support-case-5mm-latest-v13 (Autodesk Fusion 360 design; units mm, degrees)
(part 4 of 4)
sketch "Sketch74" plane through (90.7, 0, 0) normal (1, 0, 0) x axis (0, 1, 0)
  line L1 (53.302, -2.019) -> (35.6, -2.019)
  line L2 (53.302, 26.6) -> (53.302, -2.019)
  line L3 (2.6862, 26.6) -> (53.302, 26.6)
  line L4 (2.6862, -2.019) -> (2.6862, 26.6)
  line L5 (18.9875, -2.019) -> (2.6862, -2.019)
  line L6 (18.9875, 0.4) -> (18.9875, -2.019)
  line L7 (33.6, 2.4) -> (20.9875, 2.4)
  line L8 (35.6, -2.019) -> (35.6, 0.4)
  line L9 (41.9463, 5.5134) -> (37.5941, 5.5134)
  line L10 (41.7017, 1.4134) -> (41.9463, 1.4134)
  line L11 (40.5558, 1.4134) -> (41.7017, 1.4134)
  line L12 (39.1616, 1.4134) -> (40.5558, 1.4134)
  line L13 (37.8441, 1.4134) -> (39.1616, 1.4134)
  line L14 (37.5941, 1.4134) -> (37.8441, 1.4134)
  line L15 (23.4568, 21.6159) -> (25.2548, 23.2889)
  line L16 (5.2077, 18.9187) -> (4.2077, 20.7353)
  line L17 (40.1676, 9.6517) -> (39.2193, 8.064)
  line L18 (6.4, 23.1109) -> (7.4, 24.3219)
  line L19 (42.5596, 22.7691) -> (43.0662, 24.2031)
  line L20 (41.7469, 24.8866) -> (41.2404, 23.4527)
  line L21 (32.0437, 22.2712) -> (33.4647, 19.745)
  line L22 (35.4902, 15.0887) -> (34.5243, 17.4666)
  line L23 (39.4648, 19.4776) -> (39.4648, 23.3591)
  line L24 (25.9773, 6.721) -> (26.4364, 4.7387)
  line L25 (35.5538, 21.4686) -> (34.1329, 23.9948)
  line L26 (31.0052, 11.1037) -> (31.7185, 10.588)
  line L27 (1.4083, 12.8829) -> (2.8013, 15.1808)
  line L28 (32.9788, 16.2652) -> (33.9447, 13.8873)
  line L29 (18.8086, 7.587) -> (17.9793, 9.8452)
  line L30 (50.6417, 0.8202) -> (50.2324, 0.2055)
  line L31 (36.9, 23.3591) -> (36.9, 19.4776)
  line L32 (3.3483, 7.513) -> (4.3483, 10.5407)
  line L33 (2.4517, 11.4595) -> (1.4517, 8.4318)
  line L34 (17.1621, 9.4051) -> (17.9914, 7.1468)
  line L35 (33.0246, 12.4489) -> (32.3113, 12.9647)
  line L36 (18.5778, 15.5074) -> (19.089, 10.0002)
  line L37 (20.7281, 10.2234) -> (20.2169, 15.7306)
  line L38 (27.6816, 5.1617) -> (27.2225, 7.144)
  line L39 (19.5307, 19.8249) -> (22.16, 15.944)
  line L40 (3.4024, 25.3699) -> (2.7109, 24.2292)
  line L41 (10.158, 8.4337) -> (10.6467, 10.7711)
  line L42 (3.3478, 1.0989) -> (4.3745, -0.8093)
  line L43 (45.475, 24.0646) -> (46.475, 21.6425)
  line L44 (17.8581, 22.3319) -> (16.0794, 25.106)
  line L45 (1.7816, 16.0876) -> (0.3885, 13.7896)
  line L46 (23.8986, 17.6716) -> (21.2693, 21.5525)
  line L47 (3.7061, 23.3443) -> (4.3976, 24.485)
  line L48 (1.8109, 22.8539) -> (0.9351, 25.0418)
  line L49 (9.7695, 4.8354) -> (8.2332, 1.8078)
  line L50 (-0.5165, 24.1896) -> (0.3592, 22.0017)
  line L51 (6.141, 0.5848) -> (5.1143, 2.493)
  line L52 (51.59, -1.1201) -> (51.9992, -0.5054)
  line L53 (49.2483, 16.4768) -> (49.6841, 17.9192)
  line L54 (7.1055, 12.435) -> (11.5308, 19.7348)
  line L55 (55.5632, 8.2533) -> (54.5035, 10.9558)
  line L56 (53.6718, 2.0633) -> (54.6124, 4.3817)
  line L57 (8.4571, 20.1523) -> (9.15, 20.9915)
  line L58 (53.7, 23.8375) -> (50.7, 16.5711)
  line L59 (4.9, 7.3669) -> (5.9, 4.9447)
  line L60 (24.8728, 5.5249) -> (24.3728, 6.0249)
  line L61 (11.1272, 16.5692) -> (11.4959, 14.939)
  line L62 (6.4, 25.533) -> (5.4, 24.3219)
  line L63 (14.653, 23.7646) -> (16.4317, 20.9905)
  line L64 (47.325, 22.1571) -> (46.325, 24.5793)
  line L65 (9.1533, 11.2291) -> (8.6646, 8.8917)
  line L66 (48.1159, 18.614) -> (47.6802, 17.1716)
  line L67 (27.9313, 20.6361) -> (22.1786, 11.5219)
  line L68 (53.0687, 5.3003) -> (52.1282, 2.9819)
  line L69 (10.1405, 20.971) -> (5.7152, 13.6711)
  line L70 (13.1748, 24.5947) -> (12.4, 25.533)
  line L71 (40.7726, 6.7035) -> (41.7208, 8.2912)
  line L72 (2.5923, 19.4311) -> (3.5923, 17.6144)
  line L73 (51.7635, 9.5602) -> (52.6564, 11.7611)
  line L74 (53.1, 15.1178) -> (56.1, 22.3842)
  line L75 (49.0733, 22.7972) -> (49.8997, 20.6896)
  line L76 (24.2394, 24.8894) -> (22.4414, 23.2165)
  line L77 (13.3041, 15.5388) -> (12.9354, 17.169)
  line L78 (22.6272, 3.9751) -> (23.1272, 3.4751)
  line L79 (7.9, 6.1558) -> (6.9, 8.578)
  line L80 (11.4, 24.3219) -> (12.1748, 23.3836)
  line L81 (17.1803, 17.3595) -> (15.9685, 19.506)
  line L82 (51.1436, 12.6613) -> (50.2507, 10.4604)
  line L83 (54.8808, 17.4204) -> (54.1112, 15.5233)
  line L84 (50.4738, 21.0198) -> (49.6474, 23.1274)
  line L85 (25.1005, 8.8169) -> (30.8532, 17.9311)
  line L86 (40.8805, 17.1052) -> (46.2802, 3.3342)
  line L87 (14.2377, 18.0729) -> (15.4494, 15.9264)
  line L88 (55.6943, 14.5812) -> (56.464, 16.4784)
  line L89 (13.7708, 12.9212) -> (11.9937, 2.022)
  line L90 (7.65, 22.8081) -> (6.9571, 21.969)
  line L91 (9.5668, 0.8153) -> (11.1031, 3.8429)
  line L92 (38.2565, 14.808) -> (31.122, 6.5197)
  line L93 (14.9409, 1.3172) -> (16.718, 12.2164)
  line L94 (-1.1, -2.7783) -> (57.9, -2.7783)
  line L95 (32.609, 4.9036) -> (39.7435, 13.192)
  line L96 (50.3191, 5.657) -> (44.9195, 19.428)
  line L97 (53.7651, 10.5312) -> (54.8248, 7.8286)
  line L98 (15.9449, -0.1083) -> (17.5336, 3.5298)
  line L99 (19.1191, 2.8374) -> (17.5303, -0.8007)
  line L100 (16.3914, -1.2472) -> (18.6725, 3.9763)
  arc A1 centre (20.9875, 0.4) radius 2 clockwise from (18.9875, 0.4) to (20.9875, 2.4)
  arc A2 centre (33.6, 0.4) radius 2 clockwise from (33.6, 2.4) to (35.6, 0.4)
  arc A3 centre (41.9463, 3.4634) radius 2.05 clockwise from (41.9463, 5.5134) to (41.9463, 1.4134)
  arc A4 centre (37.5941, 3.4634) radius 2.05 clockwise from (37.5941, 1.4134) to (37.5941, 5.5134)
  closed curve K1 centre (18.4, 7.3669)
  closed curve K2 centre (15.2444, 12.5688)
  closed curve K3 centre (17.5707, 9.6252)
  closed curve K4 centre (32.3715, 11.5184)
  closed curve K5 centre (27.059, 4.9502)
  closed curve K6 centre (26.5999, 6.9325)
  closed curve K7 centre (31.8655, 5.7116)
  closed curve K8 centre (28.6606, 10.4917)
  closed curve K9 centre (12.2635, 11.7963)
  closed curve K10 centre (11.4, 7.3669)
  closed curve K11 centre (33.0883, 23.133)
  closed curve K12 centre (34.7175, 14.488)
  closed curve K13 centre (33.7515, 16.8659)
  closed curve K14 centre (23.6396, 10.1694)
  closed curve K15 centre (19.9085, 10.1118)
  closed curve K16 centre (31.6583, 12.0342)
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  parallel L98 L99
extrude "Extrude130" cut sketch "Sketch74" against normal blind 2.8
sketch "Sketch75" plane through (0, -3.8138, 0) normal (0, -1, 0) x axis (1, 0, 0)
  line L1 (84.2, -2.019) -> (4.6, -2.019)
  line L2 (84.2, 26.6) -> (84.2, -2.019)
  line L3 (4.6, 26.6) -> (84.2, 26.6)
  line L4 (4.6, -2.019) -> (4.6, 26.6)
  line L5 (66.3275, 20.204) -> (66.0531, 18.5962)
  line L6 (69.7087, 11.8334) -> (68.659, 10.8525)
  line L7 (2.4342, 20.7551) -> (2.0341, 19.9667)
  line L8 (5.4007, 18.5733) -> (5.8284, 20.8018)
  line L9 (11.6138, 3.0954) -> (10.1269, -0.4431)
  line L10 (4.5238, 21.1728) -> (4.096, 18.9443)
  line L11 (34.4236, 19.1639) -> (35.6936, 21.1559)
  line L12 (50.9876, 18.9404) -> (51.6298, 16.6544)
  line L13 (53.2648, 6.7818) -> (50.5709, 3.7552)
  line L14 (79.758, 14.4068) -> (79.758, 16.0903)
  line L15 (19.6345, 14.8068) -> (18.5631, 13.1676)
  line L16 (6.9567, 6.8721) -> (7.4152, 5.5068)
  line L17 (83.0491, 24.9408) -> (79.3759, 21.2565)
  line L18 (16.2289, 4.1768) -> (16.646, 2.1224)
  line L19 (20.6992, 16.5069) -> (21.1163, 17.7434)
  line L20 (42.7214, 18.2226) -> (42.3133, 16.7012)
  line L21 (11.5299, 9.2998) -> (13.972, 5.9586)
  line L22 (65.9781, 21.6037) -> (66.2842, 25.0005)
  line L23 (13.9875, 3.919) -> (13.9875, 1.4847)
  line L24 (6.0799, -0.1352) -> (4.5263, 2.913)
  line L25 (2.0102, 24.654) -> (3.1364, 23.1121)
  line L26 (15.1271, 1.4847) -> (15.1271, 3.919)
  line L27 (13.7792, 19.2179) -> (13.0569, 17.6499)
  line L28 (75.9777, -0.1832) -> (74.4989, 4.9715)
  line L29 (73.1205, 4.3857) -> (74.5993, -0.769)
  line L30 (69.4007, 9.6766) -> (70.4504, 10.6576)
  line L31 (4.3013, 24.3726) -> (3.1751, 25.9145)
  line L32 (2.5694, 5.4655) -> (2.2146, 6.8495)
  line L33 (14.1406, 16.9105) -> (14.8629, 18.4784)
  line L34 (3.4887, 2.1296) -> (5.0423, -0.9186)
  line L35 (67.1262, 9.8051) -> (71.3437, 18.4719)
  line L36 (80.797, 25.5031) -> (80.2529, 24.6752)
  line L37 (34.1619, 24.4947) -> (34.1619, 25.3852)
  line L38 (13.1032, 20.7969) -> (14.0249, 22.2071)
  line L39 (44.6849, 23.5682) -> (45.7626, 24.8067)
  line L40 (49.2171, 24.5535) -> (48.5518, 25.3633)
  line L41 (15.8325, 19.9508) -> (15.9956, 18.1421)
  line L42 (51.601, 11.8389) -> (52.7234, 8.9826)
  line L43 (63.6859, 22.3177) -> (63.3844, 24.7189)
  line L44 (48.8498, 9.8224) -> (47.3533, 5.0004)
  line L45 (46.4024, 1.7746) -> (46.3972, 3.9211)
  line L46 (20.5985, 7.418) -> (12.0847, 16.5734)
  line L47 (89, -3.6) -> (89, 28.4)
  line L48 (68.7251, 20.3596) -> (64.5076, 11.6928)
  line L49 (-2, 27.4) -> (89, 27.4)
  line L50 (-2, 28.4) -> (-2, -3.6)
  line L51 (89, 27.4) -> (89, -2.6)
  line L52 (59.5941, 8.6469) -> (56.329, 16.4708)
  line L53 (6.2954, 17.01) -> (4.0568, 5.3475)
  line L54 (-2, -2.6) -> (-2, 27.4)
  line L55 (89, 28.4) -> (-2, 28.4)
  line L56 (53.4013, 14.6609) -> (56.6664, 6.8369)
  line L57 (10.0993, 13.8384) -> (18.6132, 4.683)
  line L58 (5.5432, 4.9248) -> (7.7819, 16.5873)
  line L59 (-2, -3.6) -> (89, -3.6)
  line L60 (28.0063, 15.7339) -> (25.5219, 8.0645)
  line L61 (89, -2.6) -> (-2, -2.6)
  line L62 (29.1093, 6.343) -> (31.5937, 14.0124)
  line L63 (36.5702, 20.2977) -> (37.4886, 10.1141)
  line L64 (74.4711, 20.8505) -> (73.3253, 22.6668)
  line L65 (86.3856, 13.2262) -> (86.8678, 13.7098)
  line L66 (10.489, 3.689) -> (10.8556, 5.5991)
  line L67 (14.6001, 6.6387) -> (12.158, 9.9799)
  line L68 (74.623, 12.7502) -> (75.8256, 11.4188)
  line L69 (17.4293, 13.9143) -> (17.4293, 15.3703)
  line L70 (46.9137, -1.2094) -> (47.4316, -0.2849)
  line L71 (61.5172, 10.3053) -> (62.5376, 12.5614)
  line L72 (37.2516, 24.4317) -> (38.2032, 23.5104)
  line L73 (23.166, 22.9824) -> (21.9756, 24.5127)
  line L74 (41.0189, 10.5857) -> (40.1006, 20.7693)
  line L75 (56.533, 18.3376) -> (57.0216, 17.1668)
  line L76 (60.8879, 0.7104) -> (60.3215, -0.6556)
  line L77 (60.4977, 24.1194) -> (60.7358, 21.6443)
  line L78 (52.4803, 1.2376) -> (55.1741, 4.2642)
  line L79 (51.0499, 25.4275) -> (50.1905, 23.9384)
  line L80 (20.9378, 23.3167) -> (22.1282, 21.7864)
  line L81 (38.9926, 24.7181) -> (38.041, 25.6394)
  line L82 (58.7171, 18.1125) -> (61.268, 15.4631)
  line L83 (2.3456, 16.9649) -> (3.2227, 15.2408)
  line L84 (71.4399, 7.5697) -> (71.4045, 7.1597)
  line L85 (67.5485, 2.3996) -> (67.5515, 1.1452)
  line L86 (1.6404, 11.0419) -> (2.3688, 8.2011)
  line L87 (1.5468, 2.5042) -> (1.8665, 1.2572)
  line L88 (72.5955, 7.0073) -> (72.6309, 7.4173)
  line L89 (47.3983, 17.822) -> (44.3032, 14.3447)
  line L90 (57.199, 24.8521) -> (55.6063, 22.6977)
  line L91 (18.406, 18.4641) -> (18.2429, 20.2728)
  line L92 (45.2028, 3.9169) -> (45.208, 1.7703)
  line L93 (58.2087, 14.6147) -> (59.7175, 13.6039)
  line L94 (47.8665, 24.5292) -> (48.5318, 23.7194)
  line L95 (44.8249, 20.7679) -> (41.1449, 25.6203)
  line L96 (62.2156, 24.5015) -> (62.5172, 22.1003)
  line L97 (45.9043, 12.2335) -> (48.9994, 15.7108)
  line L98 (63.8886, 2.6664) -> (62.188, 6.2679)
  line L99 (48.9639, -0.1553) -> (49.938, -1.4397)
  line L100 (47.0075, 11.5857) -> (46.2252, 10.2303)
  line L101 (64.7983, 4.9894) -> (65.169, 6.1836)
  line L102 (54.1499, 9.813) -> (53.0275, 12.6693)
  line L103 (60.2408, 14.7611) -> (58.7321, 15.7719)
  line L104 (45.1765, 25.5622) -> (44.0988, 24.3237)
  line L105 (57.5931, 20.5219) -> (59.1858, 22.6762)
  line L106 (48.8403, 4.3168) -> (50.3368, 9.1388)
  line L107 (64.8657, 25.1898) -> (64.5596, 21.793)
  line L108 (22.5432, 19.7116) -> (17.065, 25.0157)
  line L109 (64.431, 6.5229) -> (64.0604, 5.3287)
  line L110 (55.2717, 2.9988) -> (54.2717, 1.7817)
  line L111 (50.4953, -0.8135) -> (49.5212, 0.4709)
  line L112 (34.609, 22.1803) -> (33.339, 20.1883)
  line L113 (60.6028, 5.159) -> (62.3034, 1.5575)
  line L114 (49.7536, 20.7586) -> (47.8509, 23.0339)
  line L115 (47.1794, 9.4145) -> (47.9617, 10.7699)
  line L116 (50.4509, 15.2812) -> (48.9722, 13.4074)
  line L117 (43.4727, 16.2405) -> (43.8808, 17.7618)
  line L118 (11.3914, -1.2301) -> (12.8782, 2.3083)
  line L119 (71.8969, 9.7055) -> (74.2041, 7.2494)
  line L120 (20.1914, 18.2056) -> (19.7743, 16.9691)
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  horizontal L59
  vertical L50
  horizontal L55
  vertical L47
extrude "Extrude131" cut sketch "Sketch75" against normal blind 2.8
delete_face "DeleteFace141"
delete_face "DeleteFace142"
delete_face "DeleteFace143"
extrude "Extrude132" cut sketch "Sketch75" against normal blind 2.8
extrude "Extrude133" cut of existing geometry blind -0.377
delete_face "DeleteFace144"
sketch "Sketch76" plane through (-1.8892, 0, 0) normal (-1, 0, 0) x axis (0, -1, 0)
  line L1 (-3.0601, 20.4699) -> (-15.7431, 20.4699)
  line L2 (-3.0601, 26.6) -> (-3.0601, 20.4699)
  line L3 (-52.9282, 26.6) -> (-3.0601, 26.6)
  line L4 (-52.9282, 18.2699) -> (-52.9282, 26.6)
  line L5 (-38.2931, 18.2699) -> (-52.9282, 18.2699)
  line L6 (-36.2931, 3.4699) -> (-36.2931, 16.2699)
  line L7 (-52.9282, 1.4699) -> (-38.2931, 1.4699)
  line L8 (-52.9282, -2.019) -> (-52.9282, 1.4699)
  line L9 (-3.0601, -2.019) -> (-52.9282, -2.019)
  line L10 (-3.0601, 1.4699) -> (-3.0601, -2.019)
  line L11 (-15.7431, 1.4699) -> (-3.0601, 1.4699)
  line L12 (-17.7431, 18.4699) -> (-17.7431, 3.4699)
  line L13 (-18.1431, 3.4699) -> (-18.1431, 18.4699)
  line L14 (-33.6431, 1.4699) -> (-20.1431, 1.4699)
  line L15 (-35.6431, 18.4699) -> (-35.6431, 3.4699)
  line L16 (-20.1431, 20.4699) -> (-33.6431, 20.4699)
  line L17 (-41, 22) -> (-38, 25)
  line L18 (-36, 23) -> (-39, 20)
  line L19 (-41, 20) -> (-36, 25)
  line L20 (-46.5728, 20.5747) -> (-47.6906, 23.4106)
  line L21 (-45.4106, 24.3094) -> (-44.2927, 21.4735)
  line L22 (-44.9834, 19.8841) -> (-47, 25)
  line L23 (-54.6152, 20.768) -> (-52.6332, 24.8)
  line L24 (-50.8874, 23.9419) -> (-52.8694, 19.9098)
  line L25 (-54.1714, 19.466) -> (-51.3312, 25.2439)
  line L26 (-29.4509, 23.5022) -> (-30.7563, 22.0614)
  line L27 (-32.0614, 23.2437) -> (-30.756, 24.6846)
  line L28 (-29.5123, 24.7459) -> (-32, 22)
  line L29 (-24.824, 24.2216) -> (-24.4757, 23.4985)
  line L30 (-26.4985, 22.5243) -> (-26.8468, 23.2474)
  line L31 (-26.3225, 24.7459) -> (-25, 22)
  line L32 (-19.7431, 23.6641) -> (-20.4062, 22.6032)
  line L33 (-21.7376, 23.4354) -> (-21.0745, 24.4963)
  line L34 (-19.9927, 24.7459) -> (-21.488, 22.3536)
  line L35 (-15.7371, 22.1662) -> (-16.5704, 23.4846)
  line L36 (-15.6671, 24.0555) -> (-14.8338, 22.7371)
  line L37 (-15, 22) -> (-16.4042, 24.2216)
  line L38 (-2, 24) -> (-4, 22)
  line L39 (-5, 23) -> (-3, 25)
  line L40 (-2, 25) -> (-5, 22)
  line L41 (-8.1376, 23.1062) -> (-9.5762, 21.8624)
  line L42 (-11.3324, 23.8938) -> (-9.8938, 25.1376)
  line L43 (-8, 25) -> (-11.47, 22)
  arc A1 centre (-38.2931, 16.2699) radius 2 clockwise from (-38.2931, 18.2699) to (-36.2931, 16.2699)
  arc A2 centre (-38.2931, 3.4699) radius 2 clockwise from (-36.2931, 3.4699) to (-38.2931, 1.4699)
  arc A3 centre (-15.7431, 3.4699) radius 2 clockwise from (-15.7431, 1.4699) to (-17.7431, 3.4699)
  arc A4 centre (-15.7431, 18.4699) radius 2 clockwise from (-17.7431, 18.4699) to (-15.7431, 20.4699)
  arc A5 centre (-20.1431, 18.4699) radius 2 clockwise from (-20.1431, 20.4699) to (-18.1431, 18.4699)
  arc A6 centre (-20.1431, 3.4699) radius 2 clockwise from (-18.1431, 3.4699) to (-20.1431, 1.4699)
  arc A7 centre (-33.6431, 3.4699) radius 2 clockwise from (-33.6431, 1.4699) to (-35.6431, 3.4699)
  arc A8 centre (-33.6431, 18.4699) radius 2 clockwise from (-35.6431, 18.4699) to (-33.6431, 20.4699)
  arc A9 centre (-40, 21) radius 1.4142 clockwise from (-39, 20) to (-41, 22)
  arc A10 centre (-37, 24) radius 1.4142 clockwise from (-38, 25) to (-36, 23)
  arc A11 centre (-45.4327, 21.0241) radius 1.2254 clockwise from (-44.2927, 21.4735) to (-46.5728, 20.5747)
  arc A12 centre (-46.5506, 23.86) radius 1.2254 clockwise from (-47.6906, 23.4106) to (-45.4106, 24.3094)
  arc A13 centre (-53.7423, 20.3389) radius 0.9727 clockwise from (-52.8694, 19.9098) to (-54.6152, 20.768)
  arc A14 centre (-51.7603, 24.371) radius 0.9727 clockwise from (-52.6332, 24.8) to (-50.8874, 23.9419)
  circle C1 centre (-49.5, 20.5) radius 1.4559
  circle C2 centre (-55.5292, 24.2974) radius 1
  circle C3 centre (-42.4709, 24.2475) radius 1
  arc A15 centre (-30.1035, 24.0934) radius 0.8805 clockwise from (-30.756, 24.6846) to (-29.4509, 23.5022)
  arc A16 centre (-31.4088, 22.6525) radius 0.8805 clockwise from (-30.7563, 22.0614) to (-32.0614, 23.2437)
  arc A17 centre (-25.8354, 23.7345) radius 1.1226 clockwise from (-26.8468, 23.2474) to (-24.824, 24.2216)
  arc A18 centre (-25.4871, 23.0114) radius 1.1226 clockwise from (-24.4757, 23.4985) to (-26.4985, 22.5243)
  arc A19 centre (-20.4088, 24.0802) radius 0.7851 clockwise from (-21.0745, 24.4963) to (-19.7431, 23.6641)
  arc A20 centre (-21.0719, 23.0193) radius 0.7851 clockwise from (-20.4062, 22.6032) to (-21.7376, 23.4354)
  arc A21 centre (-15.2855, 22.4516) radius 0.5343 clockwise from (-14.8338, 22.7371) to (-15.7371, 22.1662)
  arc A22 centre (-16.1188, 23.77) radius 0.5343 clockwise from (-16.5704, 23.4846) to (-15.6671, 24.0555)
  arc A23 centre (-2.5, 24.5) radius 0.7071 clockwise from (-3, 25) to (-2, 24)
  arc A24 centre (-4.5, 22.5) radius 0.7071 clockwise from (-4, 22) to (-5, 23)
  arc A25 centre (-9.0157, 24.1219) radius 1.3426 clockwise from (-9.8938, 25.1376) to (-8.1376, 23.1062)
  arc A26 centre (-10.4543, 22.8781) radius 1.3426 clockwise from (-9.5762, 21.8624) to (-11.3324, 23.8938)
  circle C4 centre (-13.5134, 24.6961) radius 0.865
  circle C5 centre (-5.7383, 24.6961) radius 0.7437
  circle C6 centre (-7, 22) radius 0.6478
  circle C7 centre (-34.5, 21.5) radius 0.5
  circle C8 centre (-33.5, 24.5) radius 0.7273
  point P40 (-36, 25)
  point P41 (-41, 20)
  point P48 (-47, 25)
  point P49 (-44.9834, 19.8841)
  point P56 (-51.3312, 25.2439)
  point P57 (-54.1714, 19.466)
  point P67 (-32, 22)
  point P68 (-29.5123, 24.7459)
  point P75 (-25, 22)
  point P76 (-26.3225, 24.7459)
  point P83 (-21.488, 22.3536)
  point P84 (-19.9927, 24.7459)
  point P91 (-16.4042, 24.2216)
  point P92 (-15, 22)
  point P99 (-5, 22)
  point P100 (-2, 25)
  point P107 (-11.47, 22)
  point P108 (-8, 25)
  tangent L17 A9
  tangent A9 L18
  parallel L17 L18
  tangent L18 A10
  tangent L17 A10
  midpoint A10 P40
  midpoint A9 P41
  tangent L20 A11
  tangent A11 L21
  parallel L20 L21
  tangent L21 A12
  tangent L20 A12
  midpoint A12 P48
  midpoint A11 P49
  tangent L23 A13
  tangent A13 L24
  parallel L23 L24
  tangent L24 A14
  tangent L23 A14
  midpoint A14 P56
  midpoint A13 P57
  tangent L26 A15
  tangent A15 L27
  parallel L26 L27
  tangent L27 A16
  tangent L26 A16
  midpoint A16 P67
  midpoint A15 P68
  tangent L29 A17
  tangent A17 L30
  parallel L29 L30
  tangent L30 A18
  tangent L29 A18
  midpoint A18 P75
  midpoint A17 P76
  tangent L32 A19
  tangent A19 L33
  parallel L32 L33
  tangent L33 A20
  tangent L32 A20
  midpoint A20 P83
  midpoint A19 P84
  tangent L35 A21
  tangent A21 L36
  parallel L35 L36
  tangent L36 A22
  tangent L35 A22
  midpoint A22 P91
  midpoint A21 P92
  tangent L38 A23
  tangent A23 L39
  parallel L38 L39
  tangent L39 A24
  tangent L38 A24
  midpoint A24 P99
  midpoint A23 P100
  tangent L41 A25
  tangent A25 L42
  parallel L41 L42
  tangent L42 A26
  tangent L41 A26
  midpoint A26 P107
  midpoint A25 P108
sketch "Sketch77" plane through (0, 59.802, 0) normal (0, 1, 0) x axis (-1, 0, 0)
  line L1 (-41.95, 9.7703) -> (-82.1997, 9.7703)
  line L2 (-83.6997, 8.2703) -> (-83.6997, 1.0303)
  line L3 (-4.6, -2.019) -> (-84.2, -2.019)
  line L4 (-84.2, 26.6) -> (-4.6, 26.6)
  line L5 (-27.3828, 10.2053) -> (-26.3624, 12.4614)
  line L6 (-5.1381, 5.072) -> (-3.2722, 3.0063)
  line L7 (-46.1786, 18.1226) -> (-46.5867, 16.6012)
  line L8 (-2.9981, -1.3127) -> (-2.3366, 0.9282)
  line L9 (-19.4993, 9.5766) -> (-18.4496, 10.5576)
  line L10 (-45.3173, 11.831) -> (-45.939, 12.5996)
  line L11 (-20.186, 1.0493) -> (-20.189, 2.3038)
  line L12 (-28.4023, 24.0194) -> (-28.1642, 21.5443)
  line L13 (-68.2008, 16.4069) -> (-67.7837, 17.6434)
  line L14 (-54.4764, 19.0639) -> (-53.2064, 21.0559)
  line L15 (-53.1812, 14.8316) -> (-54.2705, 16.2679)
  line L16 (-65.734, 22.8824) -> (-66.9244, 24.4127)
  line L17 (-9.8415, 10.7659) -> (-12.5668, 5.3983)
  line L18 (-12.9223, -0.2832) -> (-14.4011, 4.8715)
  line L19 (-31.3069, 20.4219) -> (-29.7142, 22.5762)
  line L20 (-2.0918, 4.5858) -> (-3.9578, 6.6515)
  line L21 (-22.9219, 21.5037) -> (-22.6158, 24.9005)
  line L22 (-16.3045, 6.9073) -> (-16.2691, 7.3173)
  line L23 (-5.5983, -0.712) -> (-6.5652, 1.3369)
  line L24 (-66.3568, 19.6116) -> (-71.835, 24.9157)
  line L25 (-13.5913, 8.6865) -> (-15.8985, 11.1427)
  line L26 (-82.6403, 24.2608) -> (-80.6447, 22.6649)
  line L27 (-85.0306, 8.6712) -> (-85.759, 11.5119)
  line L28 (-84.7684, 15.8258) -> (-85.6456, 17.5499)
  line L29 (-45.4273, 16.1405) -> (-45.0192, 17.6618)
  line L30 (-83.4993, 18.4733) -> (-83.0716, 20.7018)
  line L31 (-73.0675, 19.8508) -> (-72.9044, 18.0421)
  line L32 (-69.2655, 14.7068) -> (-70.3369, 13.0676)
  line L33 (-51.6484, 24.3317) -> (-50.6968, 23.4104)
  line L34 (-24.0343, 25.0898) -> (-24.3404, 21.693)
  line L35 (-84.5987, 24.2726) -> (-85.7249, 25.8145)
  line L36 (-72.7727, 15.2703) -> (-72.7727, 13.8143)
  line L37 (-48.9253, 24.2056) -> (-45.2453, 19.3532)
  line L38 (-23.0063, 2.2751) -> (-21.5727, 4.27)
  line L39 (-24.5847, 13.1452) -> (-23.7134, 15.2661)
  line L40 (-44.0751, 20.6679) -> (-47.7551, 25.5203)
  line L41 (-44.2151, 23.4682) -> (-43.1374, 24.7067)
  line L42 (-22.1037, 18.3083) -> (-21.8292, 19.916)
  line L43 (-24.469, 6.4229) -> (-24.8396, 5.2287)
  line L44 (-18.8485, 0.623) -> (-17.5492, -1.4638)
  line L45 (-4.7, -2.119) -> (-84.3, -2.119)
  line L46 (-42.9957, 12.1335) -> (-39.9006, 15.6108)
  line L47 (-84.3, 26.5) -> (-4.7, 26.5)
  line L48 (-19.1913, 11.7334) -> (-20.241, 10.7525)
  line L49 (-64.9005, 18.7336) -> (-65.1787, 17.7267)
  line L50 (-64.8028, 25.2107) -> (-65.1886, 23.8147)
  line L51 (-29.3059, 8.5469) -> (-32.571, 16.3708)
  line L52 (-17.2772, 23.7076) -> (-17.2461, 25.0398)
  line L53 (-15.4495, 25.4697) -> (-15.8828, 24.8305)
  line L54 (-20.8303, 5.8212) -> (-19.3678, 3.296)
  line L55 (-35.4987, 14.5609) -> (-32.2336, 6.7369)
  line L56 (-7.3546, 11.9738) -> (-5.4767, 9.2002)
  line L57 (-14.277, 12.6502) -> (-13.0744, 11.3188)
  line L58 (-27.4223, 13.1715) -> (-28.4427, 10.9154)
  line L59 (-90.9, 28.3) -> (-90.9, -3.7)
  line L60 (0.1, -3.7) -> (0.1, 28.3)
  line L61 (-3.4691, 11.2139) -> (-5.347, 13.9875)
  line L62 (-11.1609, 15.9903) -> (-11.1609, 14.3068)
  line L63 (0.1, 27.3) -> (0.1, -2.7)
  line L64 (-30.6913, 14.5147) -> (-29.1825, 13.5039)
  line L65 (-30.1829, 18.0125) -> (-27.632, 15.3631)
  line L66 (-69.4808, 12.2387) -> (-68.4095, 13.8779)
  line L67 (-90.9, -2.7) -> (-90.9, 27.3)
  line L68 (-20.1749, 20.2596) -> (-24.3924, 11.5928)
  line L69 (-10.6073, 3.9244) -> (-7.882, 9.292)
  line L70 (-75.7968, 20.6969) -> (-74.8751, 22.1071)
  line L71 (-9.9567, -0.5418) -> (-6.7886, 3.6975)
  line L72 (-8.2292, 5.2923) -> (-11.3972, 1.0529)
  line L73 (-39.2297, 12.4912) -> (-37.7509, 14.3651)
  line L74 (-16.05, 16.9196) -> (-16.3122, 17.9269)
  line L75 (-28.6592, 14.6611) -> (-30.1679, 15.6719)
  line L76 (-29.9941, 3.4606) -> (-32.9422, 0.1484)
  line L77 (-17.0031, 9.6055) -> (-14.6959, 7.1494)
  line L78 (-43.7235, 25.4622) -> (-44.8012, 24.2237)
  line L79 (-7.5348, 0.6591) -> (-6.5679, -1.3899)
  line L80 (-3.5405, 1.4546) -> (-4.2019, -0.7863)
  line L81 (-6.0142, 17.1124) -> (-5.1639, 16.1713)
  line L82 (-3.5675, 18.7209) -> (-3.5675, 16.8386)
  line L83 (-8.1328, 24.0744) -> (-7.5886, 24.9023)
  line L84 (-8.103, 25.4031) -> (-8.6471, 24.5752)
  line L85 (-2.5144, 13.1262) -> (-2.0322, 13.6098)
  line L86 (-4.6096, 16.9131) -> (-5.4599, 17.8543)
  line L87 (-9.142, 14.3068) -> (-9.142, 15.9903)
  line L88 (-9.8294, 22.5033) -> (-9.8294, 24.2834)
  line L89 (-7.2558, 17.8062) -> (-3.5826, 21.4905)
  line L90 (-2.6396, 14.5069) -> (-3.1218, 14.0233)
  line L91 (0.1, 28.3) -> (-90.9, 28.3)
  line L92 (-42.4165, 21.24) -> (-40.5137, 18.9647)
  line L93 (-11.3041, 24.2834) -> (-11.3041, 22.5033)
  line L94 (-20.3295, 22.1477) -> (-19.3092, 23.2998)
  line L95 (-11.7205, 13.1306) -> (-12.923, 14.4619)
  line L96 (-90.9, 27.3) -> (0.1, 27.3)
  line L97 (-90.9, -3.7) -> (0.1, -3.7)
  line L98 (-15.1839, 24.1286) -> (-14.7505, 24.7677)
  line L99 (-21.7738, 9.7051) -> (-17.5563, 18.3719)
  line L100 (-16.6253, 21.585) -> (-15.4796, 19.7687)
  line L101 (-13.3148, 22.0629) -> (-11.9711, 24.8241)
  line L102 (-16.7227, 12.8801) -> (-15.6363, 13.8954)
  line L103 (-13.1808, 25.6962) -> (-14.5245, 22.935)
  line L104 (-18.0708, 25.0682) -> (-18.1018, 23.7361)
  line L105 (-2.5108, 16.8386) -> (-2.5108, 18.7209)
  line L106 (-5.8509, 24.8408) -> (-9.5241, 21.1565)
  line L107 (-15.7795, 4.2857) -> (-14.3007, -0.869)
  line L108 (-27.519, 21.6362) -> (-27.7571, 24.1114)
  line L109 (-87.2596, 10.9419) -> (-86.5312, 8.1011)
  line L110 (-86.5544, 16.8649) -> (-85.6773, 15.1408)
  line L111 (-27.6215, -1.3435) -> (-27.055, 0.0225)
  line L112 (-31.2937, 17.4283) -> (-31.7823, 18.5991)
  line L113 (-20.5432, 24.9188) -> (-21.5635, 23.7668)
  line L114 (-70.494, 18.3641) -> (-70.6571, 20.1728)
  line L115 (-67.9622, 23.2167) -> (-66.7718, 21.6864)
  line L116 (-39.9361, -0.2553) -> (-38.962, -1.5397)
  line L117 (-26.1528, 17.4729) -> (-28.7037, 20.1223)
  line L118 (-71.4707, 13.8143) -> (-71.4707, 15.2703)
  line L119 (-25.0114, 2.5664) -> (-26.712, 6.1679)
  line L120 (-86.4658, 20.6551) -> (-86.8659, 19.8667)
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  horizontal L97
  vertical L59
  horizontal L91
  vertical L60
extrude "Extrude134" cut sketch "Sketch77" against normal blind 6
delete_face "DeleteFace145"
delete_face "DeleteFace146"
extrude "Extrude135" cut sketch "Sketch76" profile of L2 L4 L17 A9 L18 A10 L20 A11 L21 A12 L23 A13 L24 A14 C1 C2 C3 L26 A15 L27 A16 L29 A17 L30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 against normal blind 4
delete_face "DeleteFace147"
delete_face "DeleteFace148"
delete_face "DeleteFace149"
delete_face "DeleteFace150"
delete_face "DeleteFace151"
delete_face "DeleteFace152"
delete_face "DeleteFace153"
delete_face "DeleteFace154"
delete_face "DeleteFace155"
delete_face "DeleteFace156"
delete_face "DeleteFace157"
delete_face "DeleteFace158"
delete_face "DeleteFace159"
delete_face "DeleteFace160"
delete_face "DeleteFace161"
delete_face "DeleteFace162"
delete_face "DeleteFace163"
delete_face "DeleteFace164"
extrude "Extrude136" cut sketch "Sketch77" against normal blind 2.8
extrude "Extrude137" cut of existing geometry blind -0.7
extrude "Extrude138" add of existing geometry blind 0.688
delete_face "DeleteFace165"
extrude "Extrude139" cut of existing geometry blind -2
extrude "Extrude140" cut of existing geometry blind -2.519
sketch "Sketch78" plane through (0, 0, -3.519) normal (0, 0, -1) x axis (1, 0, 0)
  line L1 (-0.3892, -52.9742) -> (-0.3892, -3.0141)
  line L2 (84.2, -58.302) -> (4.6, -58.302)
  line L3 (89.2, -36.1) -> (89.2, -53.302)
  line L4 (84.9, -36.1) -> (89.2, -36.1)
  line L5 (82.4, -20.9875) -> (82.4, -33.6)
  line L6 (89.2, -18.4875) -> (84.9, -18.4875)
  line L7 (89.2, -2.6862) -> (89.2, -18.4875)
  line L8 (4.6, 2.3138) -> (84.2, 2.3138)
  circle C1 centre (83.4, -52.5) radius 1.375
  circle C2 centre (25.4038, -52.5109) radius 1.375
  circle C3 centre (25.4086, -3.5211) radius 1.375
  circle C4 centre (83.4, -3.5) radius 1.375
  arc A1 centre (4.6, -2.6862) radius 5 clockwise from (-0.3892, -3.0141) to (4.6, 2.3138)
  arc A2 centre (4.6, -53.302) radius 5 clockwise from (4.6, -58.302) to (-0.3892, -52.9742)
  arc A3 centre (84.2, -53.302) radius 5 clockwise from (89.2, -53.302) to (84.2, -58.302)
  arc A4 centre (84.9, -33.6) radius 2.5 clockwise from (84.9, -36.1) to (82.4, -33.6)
  arc A5 centre (84.9, -20.9875) radius 2.5 clockwise from (82.4, -20.9875) to (84.9, -18.4875)
  arc A6 centre (84.2, -2.6862) radius 5 clockwise from (84.2, 2.3138) to (89.2, -2.6862)
  circle C5 centre (25.4086, -3.5211) radius 3
  circle C6 centre (83.4, -3.5) radius 3
  circle C7 centre (83.4, -52.5) radius 3
  circle C8 centre (25.4038, -52.5109) radius 3
  concentric C3 C5
  concentric C4 C6
  concentric C1 C7
  concentric C2 C8
  dimension "d653" diameter C5 = 6
  dimension "d654" diameter C6 = 6
  dimension "d655" diameter C7 = 6
  dimension "d656" diameter C8 = 6
extrude "Extrude141" cut sketch "Sketch78" profile of C1 C2 C3 C4 C5 C6 C7 C8 against normal blind 2
fillet "Fillet44" radius 0.5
